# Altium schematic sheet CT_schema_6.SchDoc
size 277 x 170 mm
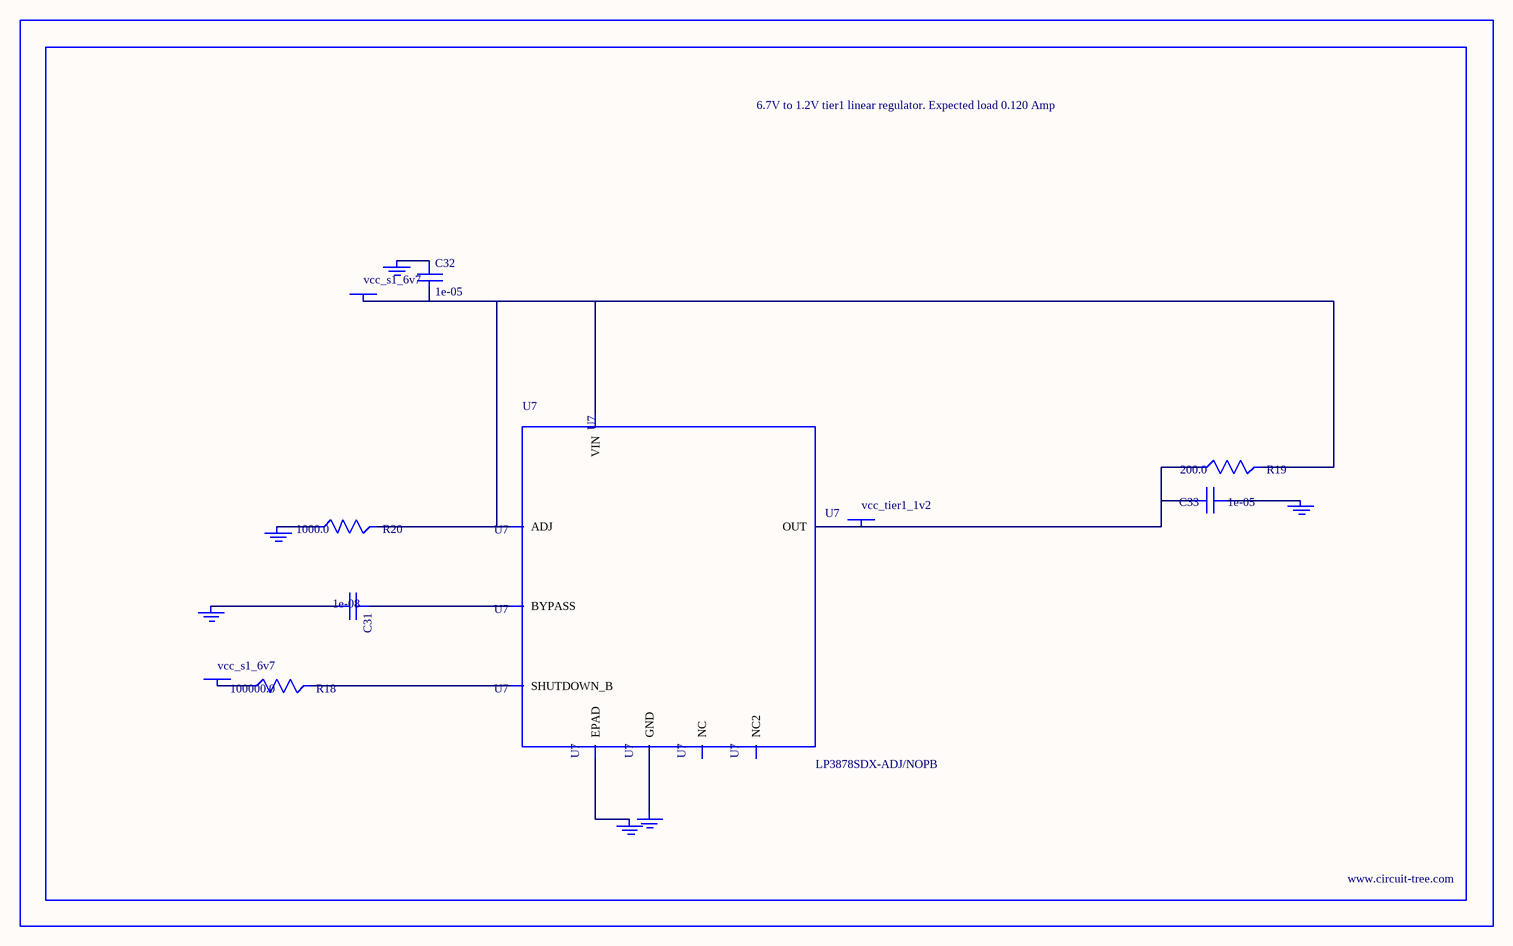
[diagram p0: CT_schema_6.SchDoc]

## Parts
BORDER5  (no value)
C31  1e-08  [C0402]
C32  1e-05  [C1206]
C33  1e-05  [C0805]
GND_INSTANCE_5_0  (no value)
GND_INSTANCE_5_1  (no value)
GND_INSTANCE_5_2  (no value)
GND_INSTANCE_5_3  (no value)
GND_INSTANCE_5_4  (no value)
GND_INSTANCE_5_5  (no value)
POWER_INSTANCE_5_0  vcc_s1_6v7
POWER_INSTANCE_5_1  vcc_s1_6v7
POWER_INSTANCE_5_2  vcc_tier1_1v2
R18  100000.0  [R0603]
R19  200.0  [R0603]
R20  1000.0  [R0603]
U7  LP3878SDX-ADJ/NOPB  [WSON-8]

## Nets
NetC31_1: C31.1 U7.1(BYPASS)
NetC31_2: C31.2 GND_INSTANCE_5_0.0(GND)
NetC32_1: C32.1 GND_INSTANCE_5_1.0(GND)
NetC32_2: C32.2 POWER_INSTANCE_5_0.0(PWR) R19.2 R20.2 U7.4(VIN) U7.6(ADJ)
NetC33_1: C33.1 GND_INSTANCE_5_2.0(GND)
NetC33_2: C33.2 POWER_INSTANCE_5_2.0(PWR) R19.1 U7.5(OUT)
NetGND_INSTANCE_5_3_0: GND_INSTANCE_5_3.0(GND) R20.1
NetGND_INSTANCE_5_4_0: GND_INSTANCE_5_4.0(GND) U7.PAD(EPAD)
NetGND_INSTANCE_5_5_0: GND_INSTANCE_5_5.0(GND) U7.3(GND)
NetPOWER_INSTANCE_5_1_0: POWER_INSTANCE_5_1.0(PWR) R18.1
NetR18_2: R18.2 U7.8(SHUTDOWN_B)

Not connected (* = marked no-connect by the designer): U7 2(NC) 7(NC2)

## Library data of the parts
BORDER5 = BORDER_PAGE5
C31 = C0402C103K3RAC
C32 = C1206C106K3RACTU
C33 = GRM219R60J106ME19D
GND_INSTANCE_5_0-GND_INSTANCE_5_5 = GND
POWER_INSTANCE_5_0-POWER_INSTANCE_5_2 = PWR
R18 = RC0603JR-07100KL
R19 = RC0603JR-07200RL
R20 = RC0603JR-071KL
